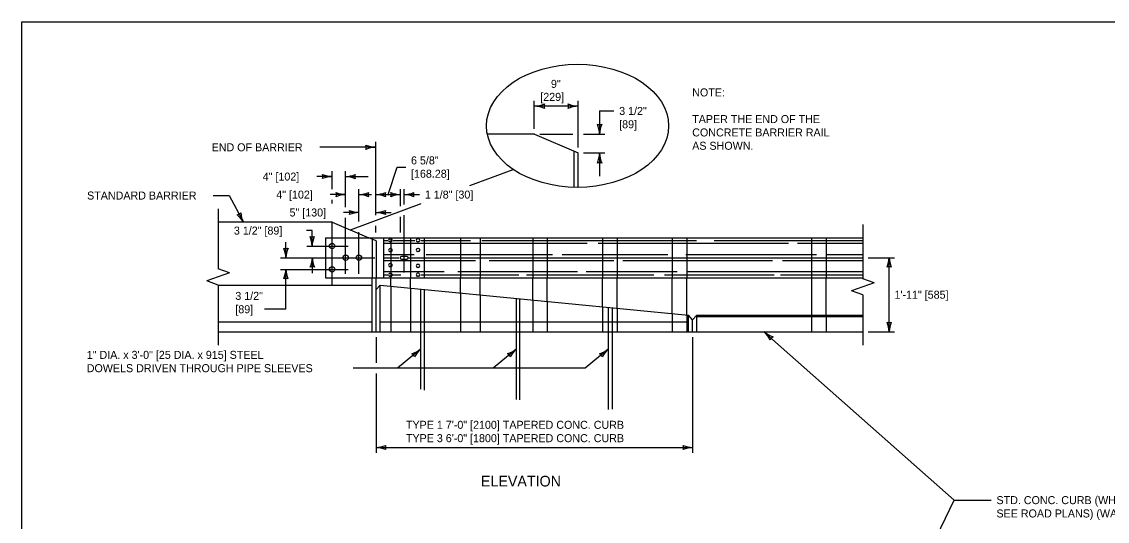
# Model space of a CAD drawing. Extents: x 49991.4 to 50021, y 49987.6 to 50011.4.
# Drawn here: x 49999.38 to 50007.52, y 49995.25 to 49999 of the extents above; entities that cross this region are included whole.
import ezdxf

# ---------------------------------------------------------------- set-up
doc = ezdxf.new("R2010")
doc.units = 0
for name, color, linetype in [('Level 1', 7, 'Continuous'), ('Level 2', 7, 'Continuous'), ('Level 3', 7, 'Continuous'), ('Level 4', 7, 'Continuous'), ('Level 5', 7, 'Continuous'), ('Level 6', 7, 'Continuous')]:
    doc.layers.add(name, color=color, linetype=linetype)

msp = doc.modelspace()

# ---------------------------------------------------------------- linework, layer by layer
at = {"layer": 'Level 1'}
for p, q in [((50003.2269, 49998.155), (50002.8749, 49998.155)), ((50003.2269, 49998.155), (50003.5565, 49998.0151)), ((50003.5263, 49997.7573), (50003.5263, 49998.028)), ((50003.5565, 49997.7571), (50003.5565, 49998.0151)), ((50001.7115, 49997.4962), (50000.8558, 49997.4962)), ((50001.7115, 49997.4962), (50001.9859, 49997.3798)), ((50001.6622, 49997.3798), (50005.6898, 49997.3798)), ((50001.6622, 49997.3798), (50001.6622, 49997.0804)), ((50002.0989, 49997.0804), (50002.0989, 49997.3798)), ((50002.0989, 49997.3599), (50002.1293, 49997.3599)), ((50002.0989, 49997.3382), (50003.6219, 49997.3382)), ((50002.1507, 49997.3711), (50002.1454, 49997.3711)), ((50002.1507, 49997.349), (50002.1454, 49997.349)), ((50002.1509, 49997.2982), (50002.1456, 49997.2982)), ((50002.168, 49997.3599), (50002.3317, 49997.3599)), ((50002.3576, 49997.3718), (50002.3522, 49997.3718)), ((50002.3576, 49997.3498), (50002.3522, 49997.3498)), ((50002.3577, 49997.2989), (50002.3524, 49997.2989)), ((50002.3764, 49997.3599), (50002.7491, 49997.3599)), ((50002.8331, 49997.3599), (50004.4431, 49997.3599)), ((50003.706, 49997.3382), (50005.1316, 49997.3382)), ((50004.5756, 49997.3599), (50005.6898, 49997.3599)), ((50005.1995, 49997.3382), (50005.6898, 49997.3382)), ((50002.0989, 49997.2548), (50002.3255, 49997.2548)), ((50002.0989, 49997.2301), (50002.2102, 49997.2301)), ((50002.1509, 49997.2762), (50002.1456, 49997.2762)), ((50002.2723, 49997.2381), (50002.2297, 49997.2381)), ((50002.2298, 49997.2198), (50002.2724, 49997.2198)), ((50002.287, 49997.2301), (50005.6898, 49997.2301)), ((50002.3577, 49997.2769), (50002.3524, 49997.2769)), ((50002.416, 49997.2548), (50003.3632, 49997.2548)), ((50003.4344, 49997.2548), (50004.2265, 49997.2548)), ((50004.3622, 49997.2548), (50005.3417, 49997.2548)), ((50005.4129, 49997.2548), (50005.6898, 49997.2548)), ((50002.0989, 49997.2083), (50002.7846, 49997.2083)), ((50002.1503, 49997.1856), (50002.145, 49997.1856)), ((50002.1503, 49997.1636), (50002.145, 49997.1636)), ((50002.3571, 49997.1798), (50002.3517, 49997.1798)), ((50002.3573, 49997.1578), (50002.3517, 49997.1578)), ((50002.888, 49997.2083), (50003.8223, 49997.2083)), ((50003.8902, 49997.2083), (50005.012, 49997.2083)), ((50005.0863, 49997.2083), (50005.6898, 49997.2083)), ((50001.6622, 49997.0804), (50002.0989, 49997.0804)), ((50002.0107, 49996.6755), (50002.0107, 49997.0804)), ((50002.0409, 49996.6755), (50002.0409, 49997.0804)), ((50002.0989, 49997.1274), (50002.5518, 49997.1274)), ((50002.0989, 49997.1026), (50002.1273, 49997.1026)), ((50002.0989, 49997.0804), (50005.6898, 49997.0804)), ((50002.1504, 49997.1128), (50002.1451, 49997.1128)), ((50002.1504, 49997.0907), (50002.1451, 49997.0907)), ((50002.1519, 49997.0171), (50002.1519, 49997.0804)), ((50002.167, 49997.1026), (50002.2253, 49997.1026)), ((50002.2989, 49997.0027), (50002.2989, 49997.0804)), ((50002.3572, 49997.1131), (50002.3519, 49997.1131)), ((50002.3574, 49997.0911), (50002.3519, 49997.0911)), ((50002.3764, 49997.1026), (50003.1111, 49997.1026)), ((50002.6521, 49997.1274), (50003.5508, 49997.1274)), ((50002.6744, 49996.9659), (50002.6744, 49997.0804)), ((50002.8213, 49996.9515), (50002.8213, 49997.0804)), ((50003.1692, 49997.1026), (50004.123, 49997.1026)), ((50003.2144, 49996.9129), (50003.2144, 49997.0804)), ((50003.3242, 49996.9021), (50003.3242, 49997.0804)), ((50003.6154, 49997.1274), (50004.2976, 49997.1274)), ((50003.7373, 49996.8616), (50003.7373, 49997.0804)), ((50003.8471, 49996.8508), (50003.8471, 49997.0804)), ((50004.2038, 49997.1026), (50005.025, 49997.1026)), ((50004.2601, 49996.8103), (50004.2601, 49997.0804)), ((50004.3686, 49997.1274), (50005.6898, 49997.1274)), ((50004.37, 49996.7995), (50004.37, 49997.0804)), ((50005.0735, 49997.1026), (50005.6898, 49997.1026)), ((50005.3052, 49997.0804), (50005.3052, 49996.8004)), ((50005.4151, 49996.8004), (50005.4151, 49997.0804)), ((50000.8558, 49997.0251), (50002.0107, 49997.0251)), ((50002.0409, 49996.9911), (50002.0708, 49997.0251)), ((50002.0708, 49996.6755), (50002.0708, 49997.0251)), ((50002.0708, 49997.0251), (50004.3832, 49996.7982)), ((50000.8558, 49996.7505), (50002.0107, 49996.7505)), ((50002.0708, 49996.7505), (50004.3832, 49996.7505)), ((50004.3832, 49996.6755), (50004.3832, 49996.7982)), ((50004.4138, 49996.765), (50004.3832, 49996.7982)), ((50004.4138, 49996.765), (50004.4452, 49996.8004)), ((50004.4138, 49996.6755), (50004.4138, 49996.765)), ((50004.4452, 49996.6755), (50004.4452, 49996.8004)), ((50004.4452, 49996.8004), (50005.6898, 49996.8004)), ((50004.4452, 49996.7886), (50005.6898, 49996.7886)), ((50000.8558, 49996.6755), (50005.6898, 49996.6755))]:
    msp.add_line(p, q, dxfattribs=at)
msp.add_lwpolyline([(49999.3835, 49998.9992), (50016.7501, 49998.9992), (50016.7501, 49987.7988), (49999.3835, 49987.7988)], close=True, dxfattribs=at)
for centre in [(50001.7103, 49997.3177), (50001.8121, 49997.2301), (50001.9115, 49997.2301), (50001.7103, 49997.1425)]:
    msp.add_circle(centre, 0.02, dxfattribs=at)
for centre, major_axis, ratio, start_param, end_param in [((50002.1454, 49997.3601), (0.011, 0), 0.998676, 1.570796, 4.712389), ((50002.1456, 49997.2872), (0.011, 0), 0.998676, 1.570796, 4.712389), ((50002.1507, 49997.3601), (0.011, 0), 0.998676, 4.712389, 7.853982), ((50002.1509, 49997.2872), (0.011, 0), 0.998676, 4.712389, 7.853982), ((50002.3522, 49997.3608), (0.011, 0), 0.998676, 1.570796, 4.712389), ((50002.3524, 49997.2879), (0.011, 0), 0.998676, 1.570796, 4.712389), ((50002.3576, 49997.3608), (0.011, 0), 0.998676, 4.712389, 7.853982), ((50002.3577, 49997.2879), (0.011, 0), 0.998676, 4.712389, 7.853982), ((50002.2298, 49997.229), (0.00923, 0), 0.988923, 1.570796, 4.712389), ((50002.2723, 49997.229), (0.00917, 0), 0.995211, 4.712389, 7.853982), ((50002.145, 49997.1746), (0.011, 0), 0.998676, 1.570796, 4.712389), ((50002.1503, 49997.1746), (0.011, 0), 0.998676, 4.712389, 7.853982), ((50002.3517, 49997.1688), (0.011, 0), 0.998676, 1.570796, 4.712389), ((50002.357, 49997.1688), (0.011, 0), 0.998676, 4.712389, 7.853982), ((50002.1451, 49997.1017), (0.011, 0), 0.998676, 1.570796, 4.712389), ((50002.1504, 49997.1017), (0.011, 0), 0.998676, 4.712389, 7.853982), ((50002.3519, 49997.1021), (0.011, 0), 0.998676, 1.570796, 4.712389), ((50002.3572, 49997.1021), (0.011, 0), 0.998676, 4.712389, 7.853982)]:
    msp.add_ellipse(centre, major_axis=major_axis, ratio=ratio, start_param=start_param, end_param=end_param, dxfattribs=at)
at = {"layer": 'Level 3'}
for p, q in [((50003.2268, 49998.195), (50003.2268, 49998.4059)), ((50003.5564, 49998.3659), (50003.2268, 49998.3659)), ((50003.5564, 49998.0552), (50003.5564, 49998.4059)), ((50003.7163, 49998.3304), (50003.7163, 49998.155)), ((50003.7163, 49998.3304), (50003.8229, 49998.3304)), ((50003.2669, 49998.155), (50003.5164, 49998.155)), ((50003.5964, 49998.155), (50003.7563, 49998.155)), ((50002.0396, 49998.0578), (50001.6175, 49998.0578)), ((50002.0396, 49998.0578), (50001.8829, 49998.0578)), ((50002.0396, 49997.5491), (50002.0396, 49998.0978)), ((50003.5964, 49998.0151), (50003.7563, 49998.0151)), ((50003.7163, 49998.0151), (50003.7163, 49997.8417)), ((50002.1309, 49997.7032), (50002.1993, 49997.9096)), ((50002.1993, 49997.9096), (50002.2623, 49997.9096)), ((50002.7431, 49997.7711), (50003.0682, 49997.8922)), ((50001.7103, 49997.8383), (50001.5954, 49997.8383)), ((50001.8121, 49997.838), (50001.9805, 49997.838)), ((50002.2222, 49997.6171), (50002.2222, 49997.7432)), ((50000.8185, 49997.6962), (50000.9381, 49997.6962)), ((50000.9381, 49997.6962), (50001.0454, 49997.4962)), ((50001.8121, 49997.7032), (50001.6971, 49997.7032)), ((50001.8487, 49997.438), (50002.3783, 49997.6353)), ((50001.9115, 49997.7032), (50002.0059, 49997.7032)), ((50002.0396, 49997.7032), (50002.2222, 49997.7032)), ((50002.2511, 49997.7032), (50002.3662, 49997.7032)), ((50001.9115, 49997.5691), (50001.7964, 49997.5691)), ((50002.0396, 49997.5691), (50002.1546, 49997.5691)), ((50002.0396, 49997.4198), (50002.0396, 49997.4691)), ((50002.2222, 49997.4198), (50002.2222, 49997.5371)), ((50001.5608, 49997.4334), (50001.5189, 49997.4334)), ((50001.5608, 49997.3177), (50001.5608, 49997.4334)), ((50001.3643, 49997.2301), (50001.3643, 49997.3458)), ((50001.5625, 49997.1144), (50001.5625, 49997.2301)), ((50005.7298, 49997.2301), (50005.927, 49997.2301)), ((50005.887, 49996.6755), (50005.887, 49997.2301)), ((50001.3643, 49996.8439), (50001.3643, 49997.1425)), ((50001.3643, 49996.8439), (50001.2045, 49996.8439)), ((50006.3751, 49995.413), (50004.9485, 49996.6755)), ((50005.7298, 49996.6755), (50005.927, 49996.6755)), ((50002.0409, 49996.6355), (50002.0409, 49996.442)), ((50004.4138, 49996.6355), (50004.4138, 49995.7674)), ((50002.3735, 49996.5442), (50002.2016, 49996.402)), ((50003.0906, 49996.5442), (50002.9187, 49996.402)), ((50003.7799, 49996.5442), (50003.608, 49996.402)), ((50003.608, 49996.402), (50001.8681, 49996.402)), ((50002.0409, 49996.362), (50002.0409, 49995.7674)), ((50002.0409, 49995.8074), (50004.4138, 49995.8074)), ((50005.5425, 49993.6846), (50006.3751, 49995.413)), ((50006.3751, 49995.413), (50006.6517, 49995.413))]:
    msp.add_line(p, q, dxfattribs=at)
for centre, radius, start, end in [((50003.2153, 49998.5986), 0.233, 272.82731, 292.07716), ((50003.2177, 49998.1438), 0.2223, 67.45601, 87.63952), ((50003.355, 49998.3659), 0.0548, 162.13882, 197.86118), ((50003.5656, 49998.5881), 0.2223, 247.45601, 267.63952), ((50003.4282, 49998.3659), 0.0548, 342.13882, 17.86118), ((50003.5679, 49998.1332), 0.233, 92.82731, 112.07716), ((50003.7163, 49998.2832), 0.0548, 252.13882, 287.86118), ((50003.4836, 49998.1435), 0.233, 2.82731, 22.07716), ((50003.9384, 49998.1459), 0.2223, 157.45601, 177.63952), ((50002.0488, 49998.2799), 0.2223, 247.45601, 267.63952), ((50001.9114, 49998.0578), 0.0548, 342.13882, 17.86118), ((50002.0511, 49997.8251), 0.233, 92.82731, 112.07716), ((50003.4942, 49998.0243), 0.2223, 337.45601, 357.63952), ((50003.949, 49998.0266), 0.233, 182.82731, 202.07716), ((50003.7163, 49997.8869), 0.0548, 72.13882, 107.86118), ((50001.7188, 49998.0452), 0.2071, 247.45601, 267.63952), ((50001.5909, 49997.8383), 0.051, 342.13882, 17.86118), ((50001.721, 49997.6215), 0.2171, 92.82731, 112.07716), ((50001.8014, 49998.0548), 0.2171, 272.82731, 292.07716), ((50001.8036, 49997.6311), 0.2071, 67.45601, 87.63952), ((50001.9316, 49997.838), 0.051, 162.13882, 197.86118), ((50001.8207, 49997.9101), 0.2071, 247.45601, 267.63952), ((50001.6927, 49997.7032), 0.051, 342.13882, 17.86118), ((50001.9008, 49997.92), 0.2171, 272.82731, 292.07716), ((50002.031, 49997.7032), 0.051, 162.13882, 197.86118), ((50002.0289, 49997.92), 0.2171, 272.82731, 292.07716), ((50002.1591, 49997.7032), 0.051, 162.13882, 197.86118), ((50002.2308, 49997.9101), 0.2071, 247.45601, 267.63952), ((50002.1028, 49997.7032), 0.051, 342.13882, 17.86118), ((50002.2404, 49997.92), 0.2171, 272.82731, 292.07716), ((50002.3706, 49997.7032), 0.051, 162.13882, 197.86118), ((50001.8228, 49997.4864), 0.2171, 92.82731, 112.07716), ((50001.903, 49997.4963), 0.2071, 67.45601, 87.63952), ((50002.0311, 49997.4963), 0.2071, 67.45601, 87.63952), ((50002.2329, 49997.4864), 0.2171, 92.82731, 112.07716), ((50002.2426, 49997.4963), 0.2071, 67.45601, 87.63952), ((50000.9889, 49997.6015), 0.051, 280.34255, 316.06491), ((50000.8594, 49997.3843), 0.2171, 31.03104, 50.28089), ((50001.2318, 49997.5865), 0.2071, 185.65974, 205.84325), ((50001.9201, 49997.776), 0.2071, 247.45601, 267.63952), ((50001.7921, 49997.5691), 0.051, 342.13882, 17.86118), ((50001.9222, 49997.3523), 0.2171, 92.82731, 112.07716), ((50002.0289, 49997.7859), 0.2171, 272.82731, 292.07716), ((50002.0311, 49997.3622), 0.2071, 67.45601, 87.63952), ((50002.1591, 49997.5691), 0.051, 162.13882, 197.86118), ((50001.5608, 49997.4371), 0.051, 252.13882, 287.86118), ((50001.344, 49997.307), 0.2171, 2.82731, 22.07716), ((50001.7677, 49997.3092), 0.2071, 157.45601, 177.63952), ((50001.3643, 49997.3495), 0.051, 252.13882, 287.86118), ((50001.1475, 49997.2194), 0.2171, 2.82731, 22.07716), ((50001.5713, 49997.2216), 0.2071, 157.45601, 177.63952), ((50001.3555, 49997.2386), 0.2071, 337.45601, 357.63952), ((50001.7793, 49997.2408), 0.2171, 182.82731, 202.07716), ((50005.6801, 49997.2386), 0.2071, 337.45601, 357.63952), ((50006.1038, 49997.2408), 0.2171, 182.82731, 202.07716), ((50001.1574, 49997.151), 0.2071, 337.45601, 357.63952), ((50001.5811, 49997.1532), 0.2171, 182.82731, 202.07716), ((50001.5625, 49997.1107), 0.051, 72.13882, 107.86118), ((50005.887, 49997.1107), 0.051, 72.13882, 107.86118), ((50001.3643, 49997.0231), 0.051, 72.13882, 107.86118), ((50005.887, 49996.7949), 0.051, 252.13882, 287.86118), ((50005.6702, 49996.6648), 0.2171, 2.82731, 22.07716), ((50006.094, 49996.667), 0.2071, 157.45601, 177.63952), ((50004.7944, 49996.5152), 0.2223, 25.94701, 46.13052), ((50005.0941, 49996.8574), 0.233, 231.31831, 250.56816), ((50005.0445, 49996.5905), 0.0548, 120.62982, 156.35218), ((50002.2458, 49996.7073), 0.2071, 287.88116, 308.06467), ((50002.2825, 49996.4668), 0.051, 22.56397, 58.28633), ((50002.5222, 49996.3861), 0.2171, 133.25246, 152.50231), ((50002.9646, 49996.7086), 0.2071, 287.28113, 307.46464), ((50002.9988, 49996.4677), 0.051, 21.96394, 57.6863), ((50003.2376, 49996.3846), 0.2171, 132.65243, 151.90228), ((50003.6523, 49996.7073), 0.2071, 287.87089, 308.0544), ((50003.689, 49996.4668), 0.051, 22.5537, 58.27606), ((50003.9286, 49996.3861), 0.2171, 133.24219, 152.49204), ((50002.0302, 49996.0242), 0.2171, 272.82731, 292.07716), ((50002.0324, 49995.6005), 0.2071, 67.45601, 87.63952), ((50002.1604, 49995.8074), 0.051, 162.13882, 197.86118), ((50004.4224, 49996.0144), 0.2071, 247.45601, 267.63952), ((50004.2944, 49995.8074), 0.051, 342.13882, 17.86118), ((50004.4245, 49995.5907), 0.2171, 92.82731, 112.07716)]:
    msp.add_arc(centre, radius, start, end, dxfattribs=at)
msp.add_ellipse((50003.5508, 49998.2186), major_axis=(0.6825, 0), ratio=0.676333, dxfattribs=at)
at = {"layer": 'Level 4'}
for p, q in [((50002.0409, 49997.3564), (50001.9859, 49997.3798)), ((50002.1519, 49997.3798), (50002.1519, 49997.0804)), ((50002.2989, 49997.3798), (50002.2989, 49997.0804)), ((50002.4031, 49997.0804), (50002.4031, 49997.3798)), ((50002.6744, 49997.3798), (50002.6744, 49997.0804)), ((50002.8213, 49997.3798), (50002.8213, 49997.0804)), ((50003.2144, 49997.3798), (50003.2144, 49997.0804)), ((50003.3242, 49997.3798), (50003.3242, 49997.0804)), ((50003.7373, 49997.3798), (50003.7373, 49997.0804)), ((50003.8471, 49997.3798), (50003.8471, 49997.0804)), ((50004.2601, 49997.3798), (50004.2601, 49997.0804)), ((50004.37, 49997.3798), (50004.37, 49997.0804)), ((50005.3052, 49997.3798), (50005.3052, 49997.0804)), ((50005.4151, 49997.3798), (50005.4151, 49997.0804)), ((50002.0107, 49997.3692), (50002.0107, 49997.0804)), ((50002.0409, 49997.3564), (50002.0409, 49997.0804)), ((50002.1519, 49997.0172), (50002.1519, 49996.6755)), ((50002.2989, 49997.0028), (50002.2989, 49996.6755)), ((50002.3735, 49996.9954), (50002.3735, 49996.244)), ((50002.4008, 49996.9927), (50002.4008, 49996.2374)), ((50002.6744, 49996.966), (50002.6744, 49996.6755)), ((50002.8213, 49996.9515), (50002.8213, 49996.6755)), ((50003.0906, 49996.925), (50003.0906, 49996.1661)), ((50003.1166, 49996.9225), (50003.1166, 49996.1643)), ((50003.2144, 49996.913), (50003.2144, 49996.6755)), ((50003.3242, 49996.9022), (50003.3242, 49996.6755)), ((50003.7373, 49996.8617), (50003.7373, 49996.6755)), ((50003.7799, 49996.8574), (50003.7799, 49996.092)), ((50003.8094, 49996.8545), (50003.8094, 49996.0938)), ((50003.8471, 49996.8509), (50003.8471, 49996.6755)), ((50004.2601, 49996.8104), (50004.2601, 49996.6755)), ((50004.37, 49996.7996), (50004.37, 49996.6755)), ((50005.3052, 49996.8019), (50005.3052, 49996.6755)), ((50005.4151, 49996.8019), (50005.4151, 49996.6755))]:
    msp.add_line(p, q, dxfattribs=at)
at = {"layer": 'Level 5'}
for p, q in [((50001.7103, 49997.7432), (50001.7103, 49997.8783)), ((50001.8121, 49997.6091), (50001.8121, 49997.878)), ((50001.9115, 49997.5014), (50001.9115, 49997.7432)), ((50002.2511, 49997.6279), (50002.2511, 49997.7432)), ((50001.7103, 49997.637), (50001.7103, 49997.6632)), ((50002.2511, 49997.1198), (50002.2511, 49997.5479)), ((50001.7103, 49997.0225), (50001.7103, 49997.5012)), ((50001.8121, 49997.1101), (50001.8121, 49997.5291)), ((50001.9115, 49997.1101), (50001.9115, 49997.4214)), ((50001.5208, 49997.3177), (50001.8303, 49997.3177)), ((50001.3243, 49997.2301), (50002.0315, 49997.2301)), ((50001.3243, 49997.1425), (50001.5625, 49997.1425)), ((50001.5625, 49997.1425), (50001.8303, 49997.1425))]:
    msp.add_line(p, q, dxfattribs=at)
at = {"layer": 'Level 6'}
for p, q in [((50000.8558, 49997.5962), (50000.8558, 49997.1462)), ((50005.6898, 49997.4798), (50005.6898, 49997.0729)), ((50000.9409, 49997.116), (50000.8558, 49997.1462)), ((50000.8558, 49997.0858), (50000.7707, 49997.0556)), ((50000.8558, 49997.0255), (50000.7707, 49997.0556)), ((50000.9409, 49997.116), (50000.8558, 49997.0858)), ((50005.775, 49997.0427), (50005.6898, 49997.0729)), ((50000.8558, 49997.0255), (50000.8558, 49996.5755)), ((50005.6898, 49997.0125), (50005.6047, 49996.9823)), ((50005.6898, 49996.9521), (50005.6047, 49996.9823)), ((50005.775, 49997.0427), (50005.6898, 49997.0125)), ((50005.6898, 49996.9521), (50005.6898, 49996.5755))]:
    msp.add_line(p, q, dxfattribs=at)

# ---------------------------------------------------------------- texts
at = {"layer": 'Level 2'}
for s, height, p in [('9"', 0.06, (50003.3514, 49998.5032)), ('[229]', 0.06, (50003.2715, 49998.4059)), ('NOTE:', 0.06, (50004.4105, 49998.4392)), ('3 1/2"', 0.06, (50003.8629, 49998.3004)), ('TAPER THE END OF THE', 0.06, (50004.4105, 49998.2392)), ('[89]', 0.06, (50003.8629, 49998.2004)), ('CONCRETE BARRIER RAIL', 0.06, (50004.4105, 49998.1392)), ('END OF BARRIER', 0.06, (50000.8074, 49998.0278)), ('AS SHOWN.', 0.06, (50004.4105, 49998.0392)), ('6 5/8" ', 0.06, (50002.3023, 49997.9296)), ('4" [102]', 0.06, (50001.1904, 49997.8083)), ('[168.28]', 0.06, (50002.3023, 49997.8296)), ('STANDARD BARRIER', 0.06, (49999.8737, 49997.6662)), ('4" [102]', 0.06, (50001.2922, 49997.6732)), ('1 1/8" [30]', 0.06, (50002.4062, 49997.6732)), ('5" [130]', 0.06, (50001.3915, 49997.5391)), ('3 1/2" [89]', 0.06, (50000.9743, 49997.4034)), ('3 1/2"', 0.06, (50000.985, 49996.9139)), ('1\'-11" [585]', 0.06, (50005.927, 49996.9228)), ('[89]', 0.06, (50000.985, 49996.8139)), ('1" DIA. x 3\'-0" [25 DIA. x 915] STEEL ', 0.06, (49999.8712, 49996.472)), ('DOWELS DRIVEN THROUGH PIPE SLEEVES', 0.06, (49999.8712, 49996.372)), ('TYPE 1 7\'-0" [2100] TAPERED CONC. CURB ', 0.06, (50002.2642, 49995.9474)), ('TYPE 3 6\'-0" [1800] TAPERED CONC. CURB ', 0.06, (50002.2642, 49995.8474)), ('ELEVATION', 0.08, (50002.8261, 49995.5152)), ('STD. CONC. CURB (WHERE REQUIRED-', 0.06, (50006.6917, 49995.3829)), ('SEE ROAD PLANS) (WARP AS NECESSARY', 0.06, (50006.6917, 49995.2829))]:
    msp.add_text(s, height=height, dxfattribs=at).set_placement(p)

doc.saveas('drawing.dxf')
